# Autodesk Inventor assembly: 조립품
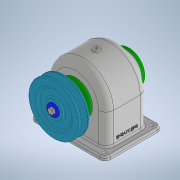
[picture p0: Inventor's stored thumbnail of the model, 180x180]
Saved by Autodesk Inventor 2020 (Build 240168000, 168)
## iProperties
Created: 2022-09
Part Number: 조립품
Document SubType Name: Assembly
Designer: Administrator
Author: Administrator
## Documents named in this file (16)
- C:\Users\Administrator\Desktop\720906V1018\조립품.iam
- C:\Users\Administrator\Desktop\720906V1018\본체.ipt
- C:\Users\Administrator\Desktop\720906V1018\축.ipt
- C:\Users\Administrator\Desktop\720906V1018\키 6 x 6 x 22.ipt
- C:\Users\Administrator\Desktop\720906V1018\뒤커버.ipt
- C:\Users\Administrator\Desktop\720906V1018\앞커버.ipt
- C:\Users\Administrator\Desktop\720906V1018\볼트 M3 x 10.ipt
- C:\Users\Administrator\Desktop\720906V1018\키 5 x 5 x 18.ipt
- C:\Users\Administrator\Desktop\720906V1018\V-벨트풀리.ipt
- C:\Users\Administrator\Desktop\720906V1018\멈춤나사 M4 x 10.ipt
- C:\Users\Administrator\Desktop\720906V1018\와셔 6 x 22.ipt
- C:\Users\Administrator\Desktop\720906V1018\육각머리볼트 M3 x 8.ipt
- C:\Users\Administrator\Desktop\720906V1018\베어링 6203.ipt
- C:\Users\Administrator\Desktop\720906V1018\칼라.ipt
- C:\Users\Administrator\Desktop\720906V1018\오일 실 17 x 30 x 8.ipt
- C:\Users\Administrator\Desktop\720906V1018\스퍼기어.ipt
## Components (9 placed, 2 different names)
1. V-벨트풀리:1 — 플러쉬:1
2. ISO 4762 M3 x 10:2
3. ISO 4762 M3 x 10:3
4. ISO 4762 M3 x 10:4
5. ISO 4762 M3 x 10:5
6. ISO 4762 M3 x 10:1
7. ISO 4762 M3 x 10:6
8. ISO 4762 M3 x 10:7
9. ISO 4762 M3 x 10:8
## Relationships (1: Flush 1)
- 플러쉬:1 [Flush]: V-벨트풀리:1
